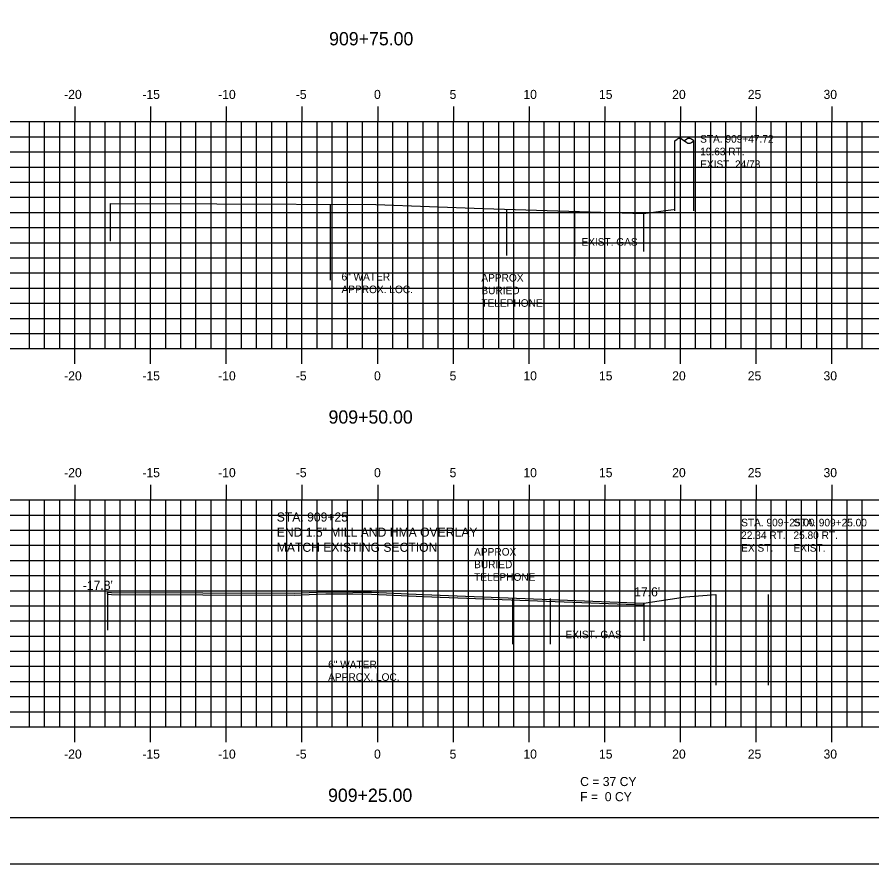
# Model space of a CAD drawing. Extents: x 1026799 to 1026969, y 394697 to 394807.
# Drawn here: x 1026858.5 to 1026915, y 394696.5 to 394752.5 of the extents above; entities that cross this region are included whole.
import ezdxf

# ---------------------------------------------------------------- set-up
doc = ezdxf.new("R2010")
doc.units = 0
for name, color, linetype in [('ANNOTATION', 7, 'Continuous'), ('BORDER', 7, 'Continuous'), ('D_Roadway_FinishedGrade', 7, 'Continuous'), ('D_Text_Monospaced', 7, 'Continuous'), ('D_Text_Standard', 7, 'Continuous'), ('H_V ANNOTATION', 7, 'Continuous'), ('MAJOR', 7, 'Continuous'), ('MINOR', 7, 'Continuous'), ('PLOT BOUNDARY', 7, 'Continuous'), ('S_Roadway_Centerline', 7, 'Continuous'), ('S_Roadway_Edge_Pavement', 7, 'Continuous'), ('S_Utilities_Pole_Power', 7, 'Continuous'), ('S_Utilities_UG_Gas_Line', 7, 'Continuous'), ('S_Utilities_UG_Sanitary_Sewer', 7, 'Continuous'), ('S_Utilities_UG_Water_Line', 7, 'Continuous')]:
    doc.layers.add(name, color=color, linetype=linetype)

msp = doc.modelspace()

# ---------------------------------------------------------------- linework, layer by layer
at = {"layer": 'BORDER'}
msp.add_line((1026807.348, 394699.607), (1026967.348, 394699.607), dxfattribs=at)
at = {"layer": 'D_Roadway_FinishedGrade'}
for p, q in [((1026864.509, 394714.379), (1026864.509, 394714.504)), ((1026899.92, 394713.663), (1026899.92, 394713.788))]:
    msp.add_line(p, q, dxfattribs=at)
for points in [[(1026864.509, 394714.504), (1026864.776, 394714.485), (1026876.835, 394714.446), (1026878.312, 394714.5), (1026878.925, 394714.523), (1026880.715, 394714.519), (1026881.948, 394714.511), (1026885.384, 394714.347), (1026886.483, 394714.301), (1026899.92, 394713.788)], [(1026864.509, 394714.379), (1026864.776, 394714.36), (1026876.835, 394714.321), (1026878.312, 394714.375), (1026878.925, 394714.398), (1026880.715, 394714.394), (1026881.948, 394714.386), (1026885.384, 394714.222), (1026886.483, 394714.176), (1026899.92, 394713.663)]]:
    msp.add_lwpolyline(points, dxfattribs=at)
at = {"layer": 'MAJOR'}
for p, q in [((1026862.348, 394746.609), (1026862.348, 394745.607)), ((1026867.348, 394746.609), (1026867.348, 394745.607)), ((1026872.348, 394746.609), (1026872.348, 394745.607)), ((1026877.348, 394746.609), (1026877.348, 394745.607)), ((1026882.348, 394746.609), (1026882.348, 394745.607)), ((1026887.348, 394746.609), (1026887.348, 394745.607)), ((1026892.348, 394746.609), (1026892.348, 394745.607)), ((1026897.348, 394746.609), (1026897.348, 394745.607)), ((1026902.348, 394746.609), (1026902.348, 394745.607)), ((1026907.348, 394746.609), (1026907.348, 394745.607)), ((1026912.348, 394746.609), (1026912.348, 394745.607)), ((1026812.348, 394745.607), (1026952.348, 394745.607)), ((1026862.348, 394730.607), (1026862.348, 394745.607)), ((1026867.348, 394730.607), (1026867.348, 394745.607)), ((1026872.348, 394730.607), (1026872.348, 394745.607)), ((1026877.348, 394730.607), (1026877.348, 394745.607)), ((1026882.348, 394730.607), (1026882.348, 394745.607)), ((1026887.348, 394730.607), (1026887.348, 394745.607)), ((1026892.348, 394730.607), (1026892.348, 394745.607)), ((1026897.348, 394730.607), (1026897.348, 394745.607)), ((1026902.348, 394730.607), (1026902.348, 394745.607)), ((1026907.348, 394730.607), (1026907.348, 394745.607)), ((1026912.348, 394730.607), (1026912.348, 394745.607)), ((1026812.348, 394740.607), (1026952.348, 394740.607)), ((1026812.348, 394735.607), (1026952.348, 394735.607)), ((1026812.348, 394730.607), (1026952.348, 394730.607)), ((1026862.348, 394729.605), (1026862.348, 394730.607)), ((1026867.348, 394729.605), (1026867.348, 394730.607)), ((1026872.348, 394729.605), (1026872.348, 394730.607)), ((1026877.348, 394729.605), (1026877.348, 394730.607)), ((1026882.348, 394729.605), (1026882.348, 394730.607)), ((1026887.348, 394729.605), (1026887.348, 394730.607)), ((1026892.348, 394729.605), (1026892.348, 394730.607)), ((1026897.348, 394729.605), (1026897.348, 394730.607)), ((1026902.348, 394729.605), (1026902.348, 394730.607)), ((1026907.348, 394729.605), (1026907.348, 394730.607)), ((1026912.348, 394729.605), (1026912.348, 394730.607)), ((1026862.348, 394721.609), (1026862.348, 394720.607)), ((1026867.348, 394721.609), (1026867.348, 394720.607)), ((1026872.348, 394721.609), (1026872.348, 394720.607)), ((1026877.348, 394721.609), (1026877.348, 394720.607)), ((1026882.348, 394721.609), (1026882.348, 394720.607)), ((1026887.348, 394721.609), (1026887.348, 394720.607)), ((1026892.348, 394721.609), (1026892.348, 394720.607)), ((1026897.348, 394721.609), (1026897.348, 394720.607)), ((1026902.348, 394721.609), (1026902.348, 394720.607)), ((1026907.348, 394721.609), (1026907.348, 394720.607)), ((1026912.348, 394721.609), (1026912.348, 394720.607)), ((1026812.348, 394720.607), (1026952.348, 394720.607)), ((1026862.348, 394705.607), (1026862.348, 394720.607)), ((1026872.348, 394705.607), (1026872.348, 394720.607)), ((1026877.348, 394705.607), (1026877.348, 394720.607)), ((1026882.348, 394705.607), (1026882.348, 394720.607)), ((1026887.348, 394705.607), (1026887.348, 394720.607)), ((1026892.348, 394705.607), (1026892.348, 394720.607)), ((1026897.348, 394705.607), (1026897.348, 394720.607)), ((1026902.348, 394705.607), (1026902.348, 394720.607)), ((1026907.348, 394705.607), (1026907.348, 394720.607)), ((1026912.348, 394705.607), (1026912.348, 394720.607)), ((1026812.348, 394715.607), (1026952.348, 394715.607)), ((1026812.348, 394710.607), (1026952.348, 394710.607)), ((1026812.348, 394705.607), (1026952.348, 394705.607)), ((1026862.348, 394704.605), (1026862.348, 394705.607)), ((1026867.348, 394704.605), (1026867.348, 394705.607)), ((1026872.348, 394704.605), (1026872.348, 394705.607)), ((1026877.348, 394704.605), (1026877.348, 394705.607)), ((1026882.348, 394704.605), (1026882.348, 394705.607)), ((1026887.348, 394704.605), (1026887.348, 394705.607)), ((1026892.348, 394704.605), (1026892.348, 394705.607)), ((1026897.348, 394704.605), (1026897.348, 394705.607)), ((1026902.348, 394704.605), (1026902.348, 394705.607)), ((1026907.348, 394704.605), (1026907.348, 394705.607)), ((1026912.348, 394704.605), (1026912.348, 394705.607))]:
    msp.add_line(p, q, dxfattribs=at)
at = {"layer": 'MINOR'}
for p, q in [((1026859.348, 394730.607), (1026859.348, 394745.607)), ((1026860.348, 394730.607), (1026860.348, 394745.607)), ((1026861.348, 394730.607), (1026861.348, 394745.607)), ((1026863.348, 394730.607), (1026863.348, 394745.607)), ((1026864.348, 394730.607), (1026864.348, 394745.607)), ((1026865.348, 394730.607), (1026865.348, 394745.607)), ((1026866.348, 394730.607), (1026866.348, 394745.607)), ((1026868.348, 394730.607), (1026868.348, 394745.607)), ((1026869.348, 394730.607), (1026869.348, 394745.607)), ((1026870.348, 394730.607), (1026870.348, 394745.607)), ((1026871.348, 394730.607), (1026871.348, 394745.607)), ((1026873.348, 394730.607), (1026873.348, 394745.607)), ((1026874.348, 394730.607), (1026874.348, 394745.607)), ((1026875.348, 394730.607), (1026875.348, 394745.607)), ((1026876.348, 394730.607), (1026876.348, 394745.607)), ((1026878.348, 394730.607), (1026878.348, 394745.607)), ((1026879.348, 394730.607), (1026879.348, 394745.607)), ((1026880.348, 394730.607), (1026880.348, 394745.607)), ((1026881.348, 394730.607), (1026881.348, 394745.607)), ((1026883.348, 394730.607), (1026883.348, 394745.607)), ((1026884.348, 394730.607), (1026884.348, 394745.607)), ((1026885.348, 394730.607), (1026885.348, 394745.607)), ((1026886.348, 394730.607), (1026886.348, 394745.607)), ((1026888.348, 394730.607), (1026888.348, 394745.607)), ((1026889.348, 394730.607), (1026889.348, 394745.607)), ((1026890.348, 394730.607), (1026890.348, 394745.607)), ((1026891.348, 394730.607), (1026891.348, 394745.607)), ((1026893.348, 394730.607), (1026893.348, 394745.607)), ((1026894.348, 394730.607), (1026894.348, 394745.607)), ((1026895.348, 394730.607), (1026895.348, 394745.607)), ((1026896.348, 394730.607), (1026896.348, 394745.607)), ((1026898.348, 394730.607), (1026898.348, 394745.607)), ((1026899.348, 394730.607), (1026899.348, 394745.607)), ((1026900.348, 394730.607), (1026900.348, 394745.607)), ((1026901.348, 394730.607), (1026901.348, 394745.607)), ((1026903.348, 394730.607), (1026903.348, 394745.607)), ((1026904.348, 394730.607), (1026904.348, 394745.607)), ((1026905.348, 394730.607), (1026905.348, 394745.607)), ((1026906.348, 394730.607), (1026906.348, 394745.607)), ((1026908.348, 394730.607), (1026908.348, 394745.607)), ((1026909.348, 394730.607), (1026909.348, 394745.607)), ((1026910.348, 394730.607), (1026910.348, 394745.607)), ((1026911.348, 394730.607), (1026911.348, 394745.607)), ((1026913.348, 394730.607), (1026913.348, 394745.607)), ((1026914.348, 394730.607), (1026914.348, 394745.607)), ((1026812.348, 394744.607), (1026952.348, 394744.607)), ((1026812.348, 394743.607), (1026952.348, 394743.607)), ((1026812.348, 394742.607), (1026952.348, 394742.607)), ((1026812.348, 394741.607), (1026952.348, 394741.607)), ((1026812.348, 394739.607), (1026952.348, 394739.607)), ((1026812.348, 394738.607), (1026952.348, 394738.607)), ((1026812.348, 394737.607), (1026952.348, 394737.607)), ((1026812.348, 394736.607), (1026952.348, 394736.607)), ((1026812.348, 394734.607), (1026952.348, 394734.607)), ((1026812.348, 394733.607), (1026952.348, 394733.607)), ((1026812.348, 394732.607), (1026952.348, 394732.607)), ((1026812.348, 394731.607), (1026952.348, 394731.607)), ((1026859.348, 394705.607), (1026859.348, 394720.607)), ((1026860.348, 394705.607), (1026860.348, 394720.607)), ((1026861.348, 394705.607), (1026861.348, 394720.607)), ((1026863.348, 394705.607), (1026863.348, 394720.607)), ((1026864.348, 394705.607), (1026864.348, 394720.607)), ((1026865.348, 394705.607), (1026865.348, 394720.607)), ((1026866.348, 394705.607), (1026866.348, 394720.607)), ((1026867.348, 394705.607), (1026867.348, 394720.607)), ((1026868.348, 394705.607), (1026868.348, 394720.607)), ((1026869.348, 394705.607), (1026869.348, 394720.607)), ((1026870.348, 394705.607), (1026870.348, 394720.607)), ((1026871.348, 394705.607), (1026871.348, 394720.607)), ((1026873.348, 394705.607), (1026873.348, 394720.607)), ((1026874.348, 394705.607), (1026874.348, 394720.607)), ((1026875.348, 394705.607), (1026875.348, 394720.607)), ((1026876.348, 394705.607), (1026876.348, 394720.607)), ((1026878.348, 394705.607), (1026878.348, 394720.607)), ((1026879.348, 394705.607), (1026879.348, 394720.607)), ((1026880.348, 394705.607), (1026880.348, 394720.607)), ((1026881.348, 394705.607), (1026881.348, 394720.607)), ((1026883.348, 394705.607), (1026883.348, 394720.607)), ((1026884.348, 394705.607), (1026884.348, 394720.607)), ((1026885.348, 394705.607), (1026885.348, 394720.607)), ((1026886.348, 394705.607), (1026886.348, 394720.607)), ((1026888.348, 394705.607), (1026888.348, 394720.607)), ((1026889.348, 394705.607), (1026889.348, 394720.607)), ((1026890.348, 394705.607), (1026890.348, 394720.607)), ((1026891.348, 394705.607), (1026891.348, 394720.607)), ((1026893.348, 394705.607), (1026893.348, 394720.607)), ((1026894.348, 394705.607), (1026894.348, 394720.607)), ((1026895.348, 394705.607), (1026895.348, 394720.607)), ((1026896.348, 394705.607), (1026896.348, 394720.607)), ((1026898.348, 394705.607), (1026898.348, 394720.607)), ((1026899.348, 394705.607), (1026899.348, 394720.607)), ((1026900.348, 394705.607), (1026900.348, 394720.607)), ((1026901.348, 394705.607), (1026901.348, 394720.607)), ((1026903.348, 394705.607), (1026903.348, 394720.607)), ((1026904.348, 394705.607), (1026904.348, 394720.607)), ((1026905.348, 394705.607), (1026905.348, 394720.607)), ((1026906.348, 394705.607), (1026906.348, 394720.607)), ((1026908.348, 394705.607), (1026908.348, 394720.607)), ((1026909.348, 394705.607), (1026909.348, 394720.607)), ((1026910.348, 394705.607), (1026910.348, 394720.607)), ((1026911.348, 394705.607), (1026911.348, 394720.607)), ((1026913.348, 394705.607), (1026913.348, 394720.607)), ((1026914.348, 394705.607), (1026914.348, 394720.607)), ((1026812.348, 394719.607), (1026952.348, 394719.607)), ((1026812.348, 394718.607), (1026952.348, 394718.607)), ((1026812.348, 394717.607), (1026952.348, 394717.607)), ((1026812.348, 394716.607), (1026952.348, 394716.607)), ((1026812.348, 394714.607), (1026952.348, 394714.607)), ((1026812.348, 394713.607), (1026952.348, 394713.607)), ((1026812.348, 394712.607), (1026952.348, 394712.607)), ((1026812.348, 394711.607), (1026952.348, 394711.607)), ((1026812.348, 394709.607), (1026952.348, 394709.607)), ((1026812.348, 394708.607), (1026952.348, 394708.607)), ((1026812.348, 394707.607), (1026952.348, 394707.607)), ((1026812.348, 394706.607), (1026952.348, 394706.607))]:
    msp.add_line(p, q, dxfattribs=at)
at = {"layer": 'PLOT BOUNDARY'}
msp.add_lwpolyline([(1026799.254, 394696.548), (1026969.254, 394696.548), (1026969.254, 394806.548), (1026799.254, 394806.548)], close=True, dxfattribs=at)
at = {"layer": 'S_Roadway_Centerline'}
for points in [[(1026864.672, 394740.201), (1026871.723, 394740.18), (1026882.224, 394740.131), (1026889.314, 394739.86), (1026899.912, 394739.526), (1026901.871, 394739.811), (1026901.871, 394739.801), (1026901.871, 394739.778)], [(1026864.509, 394714.504), (1026864.776, 394714.485), (1026876.835, 394714.446), (1026878.312, 394714.5), (1026878.925, 394714.523), (1026880.715, 394714.519), (1026881.948, 394714.511), (1026885.384, 394714.347), (1026886.483, 394714.301), (1026899.92, 394713.788), (1026902.684, 394714.205), (1026904.691, 394714.362)]]:
    msp.add_lwpolyline(points, dxfattribs=at)
at = {"layer": 'S_Roadway_Edge_Pavement'}
for p, q in [((1026864.672, 394740.201), (1026864.672, 394737.701)), ((1026899.912, 394739.526), (1026899.912, 394737.026)), ((1026864.509, 394714.504), (1026864.509, 394712.004)), ((1026899.92, 394713.788), (1026899.92, 394711.288))]:
    msp.add_line(p, q, dxfattribs=at)
at = {"layer": 'S_Utilities_Pole_Power'}
for p, q in [((1026901.98, 394739.72), (1026901.977, 394744.339)), ((1026901.98, 394744.339), (1026902.136, 394744.449)), ((1026902.449, 394744.449), (1026902.605, 394744.339)), ((1026902.762, 394744.449), (1026902.605, 394744.339)), ((1026902.605, 394744.339), (1026902.762, 394744.228)), ((1026903.23, 394744.339), (1026903.074, 394744.449)), ((1026903.074, 394744.228), (1026903.23, 394744.339)), ((1026903.23, 394739.72), (1026903.227, 394744.339))]:
    msp.add_line(p, q, dxfattribs=at)
for centre, start, end in [((1026902.292, 394744.228), 90, 125.2644), ((1026902.292, 394744.228), 54.7356, 90), ((1026902.917, 394744.228), 90, 125.2644), ((1026902.917, 394744.228), 54.7356, 90), ((1026902.917, 394744.449), 234.7356, 270), ((1026902.917, 394744.449), 270, 305.2644)]:
    msp.add_arc(centre, 0.271, start, end, dxfattribs=at)
at = {"layer": 'S_Utilities_UG_Gas_Line'}
for p, q in [((1026895.358, 394739.718), (1026895.358, 394736.718)), ((1026893.749, 394714.081), (1026893.749, 394711.081))]:
    msp.add_line(p, q, dxfattribs=at)
at = {"layer": 'S_Utilities_UG_Sanitary_Sewer'}
for p, q in [((1026904.691, 394714.362), (1026904.691, 394708.362)), ((1026908.146, 394714.359), (1026908.146, 394708.359))]:
    msp.add_line(p, q, dxfattribs=at)
at = {"layer": 'S_Utilities_UG_Water_Line'}
for p, q in [((1026879.211, 394740.126), (1026879.211, 394735.126)), ((1026890.848, 394739.811), (1026890.848, 394736.758)), ((1026878.329, 394714.5), (1026878.329, 394709.5)), ((1026891.248, 394714.119), (1026891.248, 394711.066))]:
    msp.add_line(p, q, dxfattribs=at)

# ---------------------------------------------------------------- texts
at = {"layer": 'ANNOTATION'}
for s, p in [('STA. 909+25', (1026875.682, 394719.175)), ('END 1.5" MILL AND HMA OVERLAY', (1026875.682, 394718.175)), ('MATCH EXISTING SECTION', (1026875.682, 394717.175)), ('C = 37 CY', (1026895.722, 394701.693)), ('F =  0 CY', (1026895.722, 394700.693))]:
    msp.add_text(s, height=0.6, dxfattribs=at).set_placement(p)
at = {"layer": 'D_Text_Monospaced'}
for s, height, p in [('STA. 909+47.72', 0.49998, (1026903.647, 394744.218)), ('19.63 RT.', 0.5, (1026903.647, 394743.384)), ('EXIST. 24/73', 0.49998, (1026903.647, 394742.544)), ('EXIST. GAS', 0.5, (1026895.805, 394737.409)), ('6" WATER', 0.5, (1026879.959, 394735.106)), ('APPROX', 0.5, (1026889.196, 394735.037)), ('APPROX. LOC.', 0.49998, (1026879.959, 394734.272)), ('BURIED ', 0.5, (1026889.196, 394734.203)), ('TELEPHONE', 0.5, (1026889.196, 394733.37)), ('STA. 909+25.00', 0.49998, (1026906.357, 394718.86)), ('STA. 909+25.00', 0.49998, (1026909.812, 394718.857)), ('22.34 RT.', 0.5, (1026906.357, 394718.026)), ('25.80 RT.', 0.5, (1026909.812, 394718.023)), ('APPROX', 0.5, (1026888.718, 394716.926)), ('EXIST. ', 0.5, (1026906.357, 394717.186)), ('EXIST. ', 0.5, (1026909.812, 394717.183)), ('BURIED ', 0.5, (1026888.718, 394716.093)), ('TELEPHONE', 0.5, (1026888.718, 394715.259)), ('EXIST. GAS', 0.5, (1026894.755, 394711.463)), ('6" WATER', 0.5, (1026879.077, 394709.48)), ('APPROX. LOC.', 0.49998, (1026879.077, 394708.647))]:
    msp.add_text(s, height=height, dxfattribs=at).set_placement(p)
at = {"layer": 'D_Text_Standard'}
for s, p in [("-17.8'", (1026862.873, 394714.661)), ("17.6'", (1026899.291, 394714.23))]:
    msp.add_text(s, height=0.6, dxfattribs=at).set_placement(p)
at = {"layer": 'H_V ANNOTATION'}
for s, height, p in [('909+75.00', 0.875, (1026879.14, 394750.65)), ('-20', 0.6, (1026861.641, 394747.107)), ('-15', 0.6, (1026866.804, 394747.107)), ('-10', 0.6, (1026871.812, 394747.107)), ('-5', 0.6, (1026876.938, 394747.107)), ('0', 0.6, (1026882.107, 394747.107)), ('5', 0.6, (1026887.099, 394747.107)), ('10', 0.6, (1026891.973, 394747.107)), ('15', 0.6, (1026896.965, 394747.107)), ('20', 0.6, (1026901.802, 394747.107)), ('25', 0.6, (1026906.794, 394747.107)), ('30', 0.6, (1026911.796, 394747.107)), ('-20', 0.6, (1026861.641, 394728.507)), ('-15', 0.6, (1026866.804, 394728.507)), ('-10', 0.6, (1026871.812, 394728.507)), ('-5', 0.6, (1026876.938, 394728.507)), ('0', 0.6, (1026882.107, 394728.507)), ('5', 0.6, (1026887.099, 394728.507)), ('10', 0.6, (1026891.973, 394728.507)), ('15', 0.6, (1026896.965, 394728.507)), ('20', 0.6, (1026901.802, 394728.507)), ('25', 0.6, (1026906.794, 394728.507)), ('30', 0.6, (1026911.796, 394728.507)), ('909+50.00', 0.875, (1026879.102, 394725.65)), ('-20', 0.6, (1026861.641, 394722.107)), ('-15', 0.6, (1026866.804, 394722.107)), ('-10', 0.6, (1026871.812, 394722.107)), ('-5', 0.6, (1026876.938, 394722.107)), ('0', 0.6, (1026882.107, 394722.107)), ('5', 0.6, (1026887.099, 394722.107)), ('10', 0.6, (1026891.973, 394722.107)), ('15', 0.6, (1026896.965, 394722.107)), ('20', 0.6, (1026901.802, 394722.107)), ('25', 0.6, (1026906.794, 394722.107)), ('30', 0.6, (1026911.796, 394722.107)), ('-20', 0.6, (1026861.641, 394703.507)), ('-15', 0.6, (1026866.804, 394703.507)), ('-10', 0.6, (1026871.812, 394703.507)), ('-5', 0.6, (1026876.938, 394703.507)), ('0', 0.6, (1026882.107, 394703.507)), ('5', 0.6, (1026887.099, 394703.507)), ('10', 0.6, (1026891.973, 394703.507)), ('15', 0.6, (1026896.965, 394703.507)), ('20', 0.6, (1026901.802, 394703.507)), ('25', 0.6, (1026906.794, 394703.507)), ('30', 0.6, (1026911.796, 394703.507)), ('909+25.00', 0.875, (1026879.07, 394700.65))]:
    msp.add_text(s, height=height, dxfattribs=at).set_placement(p)
at = {"layer": 'S_Roadway_Centerline'}
for s, p in [('L', (1026882.216, 394740.123)), ('C', (1026882.219, 394740.131)), ('L', (1026881.94, 394714.504)), ('C', (1026881.943, 394714.511))]:
    msp.add_text(s, height=0.0146, dxfattribs=at).set_placement(p)

doc.saveas('drawing.dxf')
